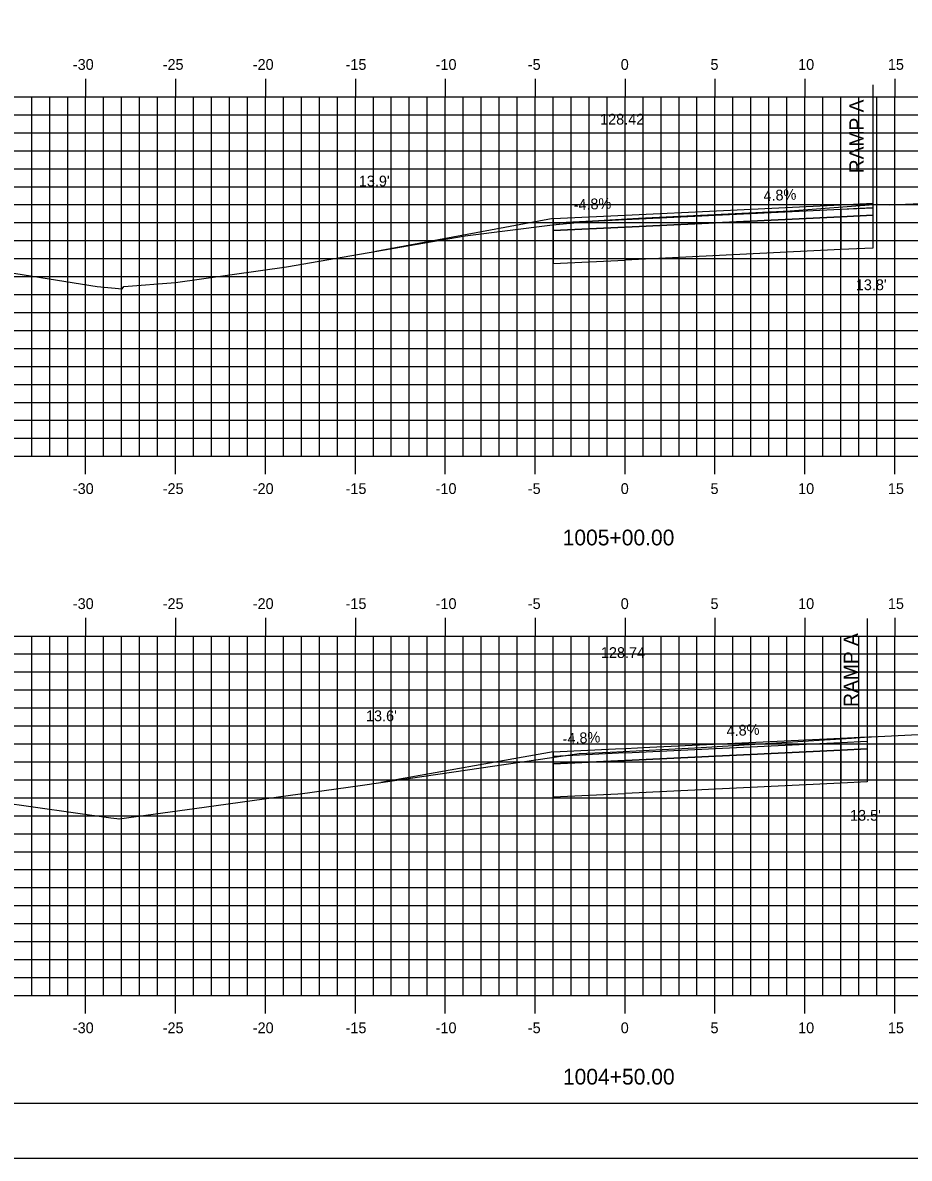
# Model space of a CAD drawing. Extents: x 851295 to 851467, y 365624 to 365734.
# Drawn here: x 851344.5 to 851393.8, y 365624 to 365687.1 of the extents above; entities that cross this region are included whole.
import ezdxf

# ---------------------------------------------------------------- set-up
doc = ezdxf.new("R2010")
doc.units = 0
for name, color, linetype in [('ANNOTATION', 7, 'Continuous'), ('BORDER', 7, 'Continuous'), ('D_Roadway_Centerline', 7, 'Continuous'), ('D_Roadway_Centerline_Text', 7, 'Continuous'), ('D_Roadway_Edge_Shoulder', 7, 'Continuous'), ('D_Roadway_Pavement', 7, 'Continuous'), ('D_Roadway_SubGrade', 7, 'Continuous'), ('D_Text_Standard', 7, 'Continuous'), ('H_V ANNOTATION', 7, 'Continuous'), ('M_Roadway_Centerline', 7, 'Continuous'), ('MAJOR', 7, 'Continuous'), ('MINOR', 7, 'Continuous'), ('PLOT BOUNDARY', 7, 'Continuous'), ('S_Roadway_Centerline', 7, 'Continuous')]:
    doc.layers.add(name, color=color, linetype=linetype)

msp = doc.modelspace()

# ---------------------------------------------------------------- linework, layer by layer
at = {"layer": 'BORDER'}
msp.add_lwpolyline([(851303.009, 365627.027), (851463.009, 365627.027), (851463.009, 365732.027), (851303.009, 365732.027)], close=True, dxfattribs=at)
at = {"layer": 'D_Roadway_Centerline'}
for p, q in [((851374.009, 365676.255), (851364.146, 365674.429)), ((851374.009, 365646.58), (851364.42, 365644.876))]:
    msp.add_line(p, q, dxfattribs=at)
for points in [[(851374.009, 365676.255), (851378.009, 365676.447), (851383.492, 365676.71), (851390.009, 365677.023), (851391.073, 365677.074), (851391.788, 365677.108)], [(851374.009, 365646.58), (851377.473, 365646.746), (851378.01, 365646.772), (851379.389, 365646.838), (851390.009, 365647.348), (851391.476, 365647.418)]]:
    msp.add_lwpolyline(points, dxfattribs=at)
at = {"layer": 'D_Roadway_Edge_Shoulder'}
for p, q in [((851390.007, 365676.773), (851391.792, 365676.859)), ((851391.788, 365676.942), (851391.788, 365676.858)), ((851378.01, 365646.772), (851378.01, 365646.522)), ((851390.009, 365647.348), (851390.009, 365647.098))]:
    msp.add_line(p, q, dxfattribs=at)
for points in [[(851378.007, 365676.197), (851390.007, 365676.773), (851390.009, 365676.773), (851390.009, 365677.023)], [(851374.009, 365676.255), (851374.007, 365676.005), (851378.007, 365676.197), (851378.009, 365676.447)]]:
    msp.add_lwpolyline(points, dxfattribs=at)
at = {"layer": 'D_Roadway_Pavement'}
for points in [[(851378.007, 365676.197), (851390.007, 365676.773), (851390.007, 365676.356), (851378.007, 365675.78)], [(851378.007, 365676.197), (851374.007, 365676.005), (851374.007, 365675.588), (851378.007, 365675.78)], [(851378.008, 365646.522), (851390.008, 365647.098), (851390.008, 365646.681), (851378.008, 365646.105)], [(851378.008, 365646.522), (851374.008, 365646.33), (851374.008, 365645.913), (851378.008, 365646.105)]]:
    msp.add_lwpolyline(points, close=True, dxfattribs=at)
for points in [[(851391.788, 365676.441), (851390.007, 365676.356), (851390.007, 365676.773), (851391.788, 365676.858)], [(851391.475, 365646.751), (851390.008, 365646.681), (851390.008, 365647.098), (851391.475, 365647.168)]]:
    msp.add_lwpolyline(points, dxfattribs=at)
at = {"layer": 'D_Roadway_SubGrade'}
for p, q in [((851391.788, 365683.689), (851391.788, 365676.942)), ((851391.788, 365676.942), (851391.786, 365674.608)), ((851391.476, 365653.998), (851391.476, 365647.251)), ((851391.476, 365647.418), (851391.473, 365644.918))]:
    msp.add_line(p, q, dxfattribs=at)
for points in [[(851378.007, 365675.78), (851374.007, 365675.588), (851374.007, 365676.088), (851374.007, 365676.255), (851374.007, 365673.755), (851378.007, 365673.947)], [(851378.007, 365675.78), (851390.007, 365676.356), (851390.007, 365674.523), (851378.007, 365673.947)], [(851378.008, 365646.105), (851374.008, 365645.913), (851374.008, 365646.413), (851374.008, 365646.58), (851374.008, 365644.08), (851378.008, 365644.272)], [(851378.008, 365646.105), (851390.008, 365646.681), (851390.008, 365644.848), (851378.008, 365644.272)]]:
    msp.add_lwpolyline(points, close=True, dxfattribs=at)
for points in [[(851391.786, 365674.608), (851390.007, 365674.523), (851390.007, 365676.356), (851391.788, 365676.441)], [(851391.473, 365644.918), (851390.008, 365644.848), (851390.008, 365646.681), (851391.475, 365646.751)]]:
    msp.add_lwpolyline(points, dxfattribs=at)
at = {"layer": 'MAJOR'}
for p, q in [((851348.009, 365684.029), (851348.009, 365683.027)), ((851353.009, 365684.029), (851353.009, 365683.027)), ((851358.009, 365684.029), (851358.009, 365683.027)), ((851363.009, 365684.029), (851363.009, 365683.027)), ((851368.009, 365684.029), (851368.009, 365683.027)), ((851373.009, 365684.029), (851373.009, 365683.027)), ((851378.009, 365684.029), (851378.009, 365683.027)), ((851383.009, 365684.029), (851383.009, 365683.027)), ((851388.009, 365684.029), (851388.009, 365683.027)), ((851393.009, 365684.029), (851393.009, 365683.027)), ((851308.009, 365683.027), (851448.009, 365683.027)), ((851308.009, 365683.027), (851448.009, 365683.027)), ((851348.009, 365663.027), (851348.009, 365683.027)), ((851353.009, 365663.027), (851353.009, 365683.027)), ((851358.009, 365663.027), (851358.009, 365683.027)), ((851363.009, 365663.027), (851363.009, 365683.027)), ((851368.009, 365663.027), (851368.009, 365683.027)), ((851373.009, 365663.027), (851373.009, 365683.027)), ((851378.009, 365663.027), (851378.009, 365683.027)), ((851383.009, 365663.027), (851383.009, 365683.027)), ((851388.009, 365663.027), (851388.009, 365683.027)), ((851393.009, 365663.027), (851393.009, 365683.027)), ((851308.009, 365678.027), (851448.009, 365678.027)), ((851308.009, 365673.027), (851448.009, 365673.027)), ((851308.009, 365668.027), (851448.009, 365668.027)), ((851308.009, 365663.027), (851448.009, 365663.027)), ((851308.009, 365663.027), (851448.009, 365663.027)), ((851348.009, 365662.025), (851348.009, 365663.027)), ((851353.009, 365662.025), (851353.009, 365663.027)), ((851358.009, 365662.025), (851358.009, 365663.027)), ((851363.009, 365662.025), (851363.009, 365663.027)), ((851368.009, 365662.025), (851368.009, 365663.027)), ((851373.009, 365662.025), (851373.009, 365663.027)), ((851378.009, 365662.025), (851378.009, 365663.027)), ((851383.009, 365662.025), (851383.009, 365663.027)), ((851388.009, 365662.025), (851388.009, 365663.027)), ((851393.009, 365662.025), (851393.009, 365663.027)), ((851348.009, 365654.029), (851348.009, 365653.027)), ((851353.009, 365654.029), (851353.009, 365653.027)), ((851358.009, 365654.029), (851358.009, 365653.027)), ((851363.009, 365654.029), (851363.009, 365653.027)), ((851368.009, 365654.029), (851368.009, 365653.027)), ((851373.009, 365654.029), (851373.009, 365653.027)), ((851378.009, 365654.029), (851378.009, 365653.027)), ((851383.009, 365654.029), (851383.009, 365653.027)), ((851388.009, 365654.029), (851388.009, 365653.027)), ((851393.009, 365654.029), (851393.009, 365653.027)), ((851308.009, 365653.027), (851448.009, 365653.027)), ((851308.009, 365653.027), (851448.009, 365653.027)), ((851348.009, 365633.027), (851348.009, 365653.027)), ((851353.009, 365633.027), (851353.009, 365653.027)), ((851358.009, 365633.027), (851358.009, 365653.027)), ((851363.009, 365633.027), (851363.009, 365653.027)), ((851368.009, 365633.027), (851368.009, 365653.027)), ((851373.009, 365633.027), (851373.009, 365653.027)), ((851378.009, 365633.027), (851378.009, 365653.027)), ((851383.009, 365633.027), (851383.009, 365653.027)), ((851388.009, 365633.027), (851388.009, 365653.027)), ((851393.009, 365633.027), (851393.009, 365653.027)), ((851308.009, 365648.027), (851448.009, 365648.027)), ((851308.009, 365643.027), (851448.009, 365643.027)), ((851308.009, 365638.027), (851448.009, 365638.027)), ((851308.009, 365633.027), (851448.009, 365633.027)), ((851308.009, 365633.027), (851448.009, 365633.027)), ((851348.009, 365632.025), (851348.009, 365633.027)), ((851353.009, 365632.025), (851353.009, 365633.027)), ((851358.009, 365632.025), (851358.009, 365633.027)), ((851363.009, 365632.025), (851363.009, 365633.027)), ((851368.009, 365632.025), (851368.009, 365633.027)), ((851373.009, 365632.025), (851373.009, 365633.027)), ((851378.009, 365632.025), (851378.009, 365633.027)), ((851383.009, 365632.025), (851383.009, 365633.027)), ((851388.009, 365632.025), (851388.009, 365633.027)), ((851393.009, 365632.025), (851393.009, 365633.027))]:
    msp.add_line(p, q, dxfattribs=at)
at = {"layer": 'MINOR'}
for p, q in [((851345.009, 365663.027), (851345.009, 365683.027)), ((851346.009, 365663.027), (851346.009, 365683.027)), ((851347.009, 365663.027), (851347.009, 365683.027)), ((851349.009, 365663.027), (851349.009, 365683.027)), ((851350.009, 365663.027), (851350.009, 365683.027)), ((851351.009, 365663.027), (851351.009, 365683.027)), ((851352.009, 365663.027), (851352.009, 365683.027)), ((851354.009, 365663.027), (851354.009, 365683.027)), ((851355.009, 365663.027), (851355.009, 365683.027)), ((851356.009, 365663.027), (851356.009, 365683.027)), ((851357.009, 365663.027), (851357.009, 365683.027)), ((851359.009, 365663.027), (851359.009, 365683.027)), ((851360.009, 365663.027), (851360.009, 365683.027)), ((851361.009, 365663.027), (851361.009, 365683.027)), ((851362.009, 365663.027), (851362.009, 365683.027)), ((851364.009, 365663.027), (851364.009, 365683.027)), ((851365.009, 365663.027), (851365.009, 365683.027)), ((851366.009, 365663.027), (851366.009, 365683.027)), ((851367.009, 365663.027), (851367.009, 365683.027)), ((851369.009, 365663.027), (851369.009, 365683.027)), ((851370.009, 365663.027), (851370.009, 365683.027)), ((851371.009, 365663.027), (851371.009, 365683.027)), ((851372.009, 365663.027), (851372.009, 365683.027)), ((851374.009, 365663.027), (851374.009, 365683.027)), ((851375.009, 365663.027), (851375.009, 365683.027)), ((851376.009, 365663.027), (851376.009, 365683.027)), ((851377.009, 365663.027), (851377.009, 365683.027)), ((851379.009, 365663.027), (851379.009, 365683.027)), ((851380.009, 365663.027), (851380.009, 365683.027)), ((851381.009, 365663.027), (851381.009, 365683.027)), ((851382.009, 365663.027), (851382.009, 365683.027)), ((851384.009, 365663.027), (851384.009, 365683.027)), ((851385.009, 365663.027), (851385.009, 365683.027)), ((851386.009, 365663.027), (851386.009, 365683.027)), ((851387.009, 365663.027), (851387.009, 365683.027)), ((851389.009, 365663.027), (851389.009, 365683.027)), ((851390.009, 365663.027), (851390.009, 365683.027)), ((851391.009, 365663.027), (851391.009, 365683.027)), ((851392.009, 365663.027), (851392.009, 365683.027)), ((851308.009, 365682.027), (851448.009, 365682.027)), ((851308.009, 365681.027), (851448.009, 365681.027)), ((851308.009, 365680.027), (851448.009, 365680.027)), ((851308.009, 365679.027), (851448.009, 365679.027)), ((851308.009, 365677.027), (851448.009, 365677.027)), ((851308.009, 365676.027), (851448.009, 365676.027)), ((851308.009, 365675.027), (851448.009, 365675.027)), ((851308.009, 365674.027), (851448.009, 365674.027)), ((851308.009, 365672.027), (851448.009, 365672.027)), ((851308.009, 365671.027), (851448.009, 365671.027)), ((851308.009, 365670.027), (851448.009, 365670.027)), ((851308.009, 365669.027), (851448.009, 365669.027)), ((851308.009, 365667.027), (851448.009, 365667.027)), ((851308.009, 365666.027), (851448.009, 365666.027)), ((851308.009, 365665.027), (851448.009, 365665.027)), ((851308.009, 365664.027), (851448.009, 365664.027)), ((851345.009, 365633.027), (851345.009, 365653.027)), ((851346.009, 365633.027), (851346.009, 365653.027)), ((851347.009, 365633.027), (851347.009, 365653.027)), ((851349.009, 365633.027), (851349.009, 365653.027)), ((851350.009, 365633.027), (851350.009, 365653.027)), ((851351.009, 365633.027), (851351.009, 365653.027)), ((851352.009, 365633.027), (851352.009, 365653.027)), ((851354.009, 365633.027), (851354.009, 365653.027)), ((851355.009, 365633.027), (851355.009, 365653.027)), ((851356.009, 365633.027), (851356.009, 365653.027)), ((851357.009, 365633.027), (851357.009, 365653.027)), ((851359.009, 365633.027), (851359.009, 365653.027)), ((851360.009, 365633.027), (851360.009, 365653.027)), ((851361.009, 365633.027), (851361.009, 365653.027)), ((851362.009, 365633.027), (851362.009, 365653.027)), ((851364.009, 365633.027), (851364.009, 365653.027)), ((851365.009, 365633.027), (851365.009, 365653.027)), ((851366.009, 365633.027), (851366.009, 365653.027)), ((851367.009, 365633.027), (851367.009, 365653.027)), ((851369.009, 365633.027), (851369.009, 365653.027)), ((851370.009, 365633.027), (851370.009, 365653.027)), ((851371.009, 365633.027), (851371.009, 365653.027)), ((851372.009, 365633.027), (851372.009, 365653.027)), ((851374.009, 365633.027), (851374.009, 365653.027)), ((851375.009, 365633.027), (851375.009, 365653.027)), ((851376.009, 365633.027), (851376.009, 365653.027)), ((851377.009, 365633.027), (851377.009, 365653.027)), ((851379.009, 365633.027), (851379.009, 365653.027)), ((851380.009, 365633.027), (851380.009, 365653.027)), ((851381.009, 365633.027), (851381.009, 365653.027)), ((851382.009, 365633.027), (851382.009, 365653.027)), ((851384.009, 365633.027), (851384.009, 365653.027)), ((851385.009, 365633.027), (851385.009, 365653.027)), ((851386.009, 365633.027), (851386.009, 365653.027)), ((851387.009, 365633.027), (851387.009, 365653.027)), ((851389.009, 365633.027), (851389.009, 365653.027)), ((851390.009, 365633.027), (851390.009, 365653.027)), ((851391.009, 365633.027), (851391.009, 365653.027)), ((851392.009, 365633.027), (851392.009, 365653.027)), ((851308.009, 365652.027), (851448.009, 365652.027)), ((851308.009, 365651.027), (851448.009, 365651.027)), ((851308.009, 365650.027), (851448.009, 365650.027)), ((851308.009, 365649.027), (851448.009, 365649.027)), ((851308.009, 365647.027), (851448.009, 365647.027)), ((851308.009, 365646.027), (851448.009, 365646.027)), ((851308.009, 365645.027), (851448.009, 365645.027)), ((851308.009, 365644.027), (851448.009, 365644.027)), ((851308.009, 365642.027), (851448.009, 365642.027)), ((851308.009, 365641.027), (851448.009, 365641.027)), ((851308.009, 365640.027), (851448.009, 365640.027)), ((851308.009, 365639.027), (851448.009, 365639.027)), ((851308.009, 365637.027), (851448.009, 365637.027)), ((851308.009, 365636.027), (851448.009, 365636.027)), ((851308.009, 365635.027), (851448.009, 365635.027)), ((851308.009, 365634.027), (851448.009, 365634.027))]:
    msp.add_line(p, q, dxfattribs=at)
at = {"layer": 'PLOT BOUNDARY'}
msp.add_lwpolyline([(851294.916, 365623.968), (851464.916, 365623.968), (851464.916, 365733.968), (851294.916, 365733.968)], close=True, dxfattribs=at)
at = {"layer": 'S_Roadway_Centerline'}
for points in [[(851308.009, 365675.813), (851312.084, 365675.932), (851312.445, 365675.937), (851315.003, 365676.07), (851322.211, 365676.269), (851324.411, 365676.188), (851333.03, 365674.916), (851334.236, 365674.715), (851341.329, 365673.638), (851348.657, 365672.481), (851350.032, 365672.35), (851350.133, 365672.476), (851353.011, 365672.688), (851359.173, 365673.57), (851369.119, 365675.289), (851373.98, 365675.895), (851376.532, 365676.152), (851378.747, 365676.283), (851387.192, 365676.691), (851392.071, 365677.045), (851392.707, 365677.023), (851396.692, 365677.186)], [(851308.009, 365646.198), (851311.951, 365646.335), (851315.739, 365646.443), (851323.169, 365646.595), (851323.675, 365646.586), (851329.312, 365645.752), (851329.563, 365645.712), (851330.289, 365645.587), (851338.912, 365644.4), (851349.404, 365642.917), (851349.749, 365642.867), (851349.863, 365642.855), (851349.867, 365642.85), (851354.606, 365643.511), (851363.283, 365644.706), (851364.42, 365644.876), (851375.456, 365646.49), (851377.185, 365646.568), (851382.249, 365646.825), (851390.604, 365647.344), (851391.561, 365647.414), (851391.713, 365647.416), (851396.158, 365647.634)]]:
    msp.add_lwpolyline(points, dxfattribs=at)

# ---------------------------------------------------------------- texts
at = {"layer": 'ANNOTATION'}
for s, height, rotation, p in [('RAMP A', 0.8, 90, (851391.281, 365678.773)), ('4.8%', 0.6, 2.74792, (851385.719, 365677.218)), ('-4.8%', 0.6, 2.74809, (851375.162, 365676.711)), ('RAMP A', 0.8, 90, (851390.969, 365649.082)), ('4.8%', 0.6, 2.74814, (851383.668, 365647.445)), ('-4.8%', 0.6, 2.74752, (851374.549, 365647.007))]:
    msp.add_text(s, height=height, rotation=rotation, dxfattribs=at).set_placement(p)
at = {"layer": 'D_Roadway_Centerline'}
for s, p in [('C', (851378.004, 365676.447)), ('L', (851378.009, 365676.439)), ('C', (851378.004, 365646.772)), ('L', (851378.01, 365646.764))]:
    msp.add_text(s, height=0.0146, dxfattribs=at).set_placement(p)
at = {"layer": 'D_Roadway_Centerline_Text'}
for s, p in [('128.42', (851376.621, 365681.479)), ('128.74', (851376.666, 365651.804))]:
    msp.add_text(s, height=0.6, dxfattribs=at).set_placement(p)
at = {"layer": 'D_Text_Standard'}
for s, p in [("13.9'", (851363.202, 365678.04)), ("13.8'", (851390.842, 365672.267)), ("13.6'", (851363.602, 365648.287)), ("13.5'", (851390.521, 365642.749))]:
    msp.add_text(s, height=0.6, dxfattribs=at).set_placement(p)
at = {"layer": 'H_V ANNOTATION'}
for s, height, p in [('-30', 0.6, (851347.297, 365684.527)), ('-25', 0.6, (851352.295, 365684.527)), ('-20', 0.6, (851357.303, 365684.527)), ('-15', 0.6, (851362.466, 365684.527)), ('-10', 0.6, (851367.474, 365684.527)), ('-5', 0.6, (851372.6, 365684.527)), ('0', 0.6, (851377.768, 365684.527)), ('5', 0.6, (851382.76, 365684.527)), ('10', 0.6, (851387.634, 365684.527)), ('15', 0.6, (851392.626, 365684.527)), ('-30', 0.6, (851347.297, 365660.927)), ('-25', 0.6, (851352.295, 365660.927)), ('-20', 0.6, (851357.303, 365660.927)), ('-15', 0.6, (851362.466, 365660.927)), ('-10', 0.6, (851367.474, 365660.927)), ('-5', 0.6, (851372.6, 365660.927)), ('0', 0.6, (851377.768, 365660.927)), ('5', 0.6, (851382.76, 365660.927)), ('10', 0.6, (851387.634, 365660.927)), ('15', 0.6, (851392.626, 365660.927)), ('1005+00.00', 0.875, (851374.537, 365658.07)), ('-30', 0.6, (851347.297, 365654.527)), ('-25', 0.6, (851352.295, 365654.527)), ('-20', 0.6, (851357.303, 365654.527)), ('-15', 0.6, (851362.466, 365654.527)), ('-10', 0.6, (851367.474, 365654.527)), ('-5', 0.6, (851372.6, 365654.527)), ('0', 0.6, (851377.768, 365654.527)), ('5', 0.6, (851382.76, 365654.527)), ('10', 0.6, (851387.634, 365654.527)), ('15', 0.6, (851392.626, 365654.527)), ('-30', 0.6, (851347.297, 365630.927)), ('-25', 0.6, (851352.295, 365630.927)), ('-20', 0.6, (851357.303, 365630.927)), ('-15', 0.6, (851362.466, 365630.927)), ('-10', 0.6, (851367.474, 365630.927)), ('-5', 0.6, (851372.6, 365630.927)), ('0', 0.6, (851377.768, 365630.927)), ('5', 0.6, (851382.76, 365630.927)), ('10', 0.6, (851387.634, 365630.927)), ('15', 0.6, (851392.626, 365630.927)), ('1004+50.00', 0.875, (851374.552, 365628.07))]:
    msp.add_text(s, height=height, dxfattribs=at).set_placement(p)
at = {"layer": 'M_Roadway_Centerline'}
for s, p in [('C', (851392.066, 365677.045)), ('L', (851392.071, 365677.038)), ('C', (851391.556, 365647.414)), ('L', (851391.561, 365647.407))]:
    msp.add_text(s, height=0.0146, dxfattribs=at).set_placement(p)

doc.saveas('drawing.dxf')
